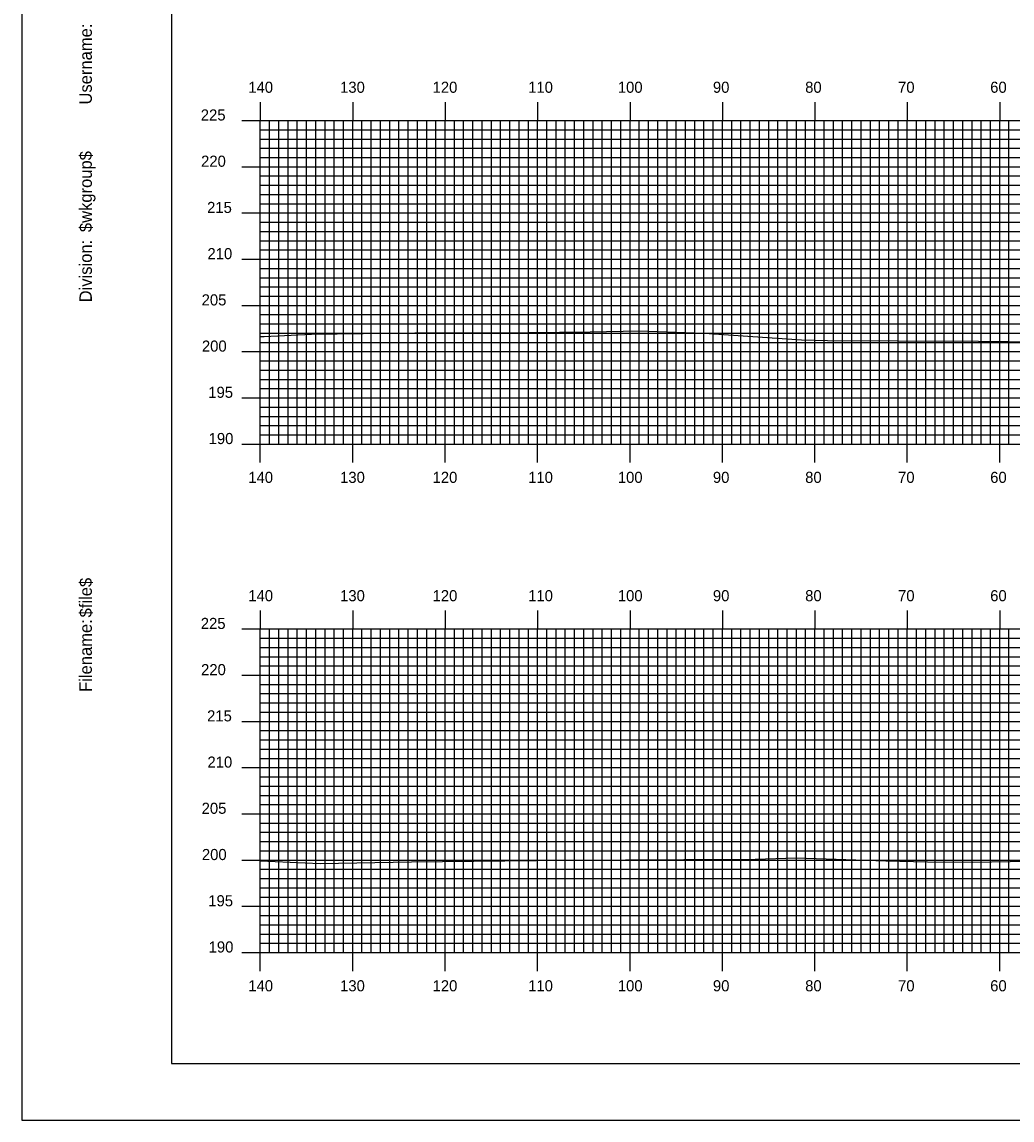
# Model space of a CAD drawing. Extents: x 1811767 to 1812110, y 442591 to 442811.
# Drawn here: x 1811767.1 to 1811874.3, y 442590.5 to 442709.3 of the extents above; entities that cross this region are included whole.
import ezdxf

# ---------------------------------------------------------------- set-up
doc = ezdxf.new("R2010")
doc.units = 0
for name, color, linetype in [('BORDER', 7, 'Continuous'), ('H_V ANNOTATION', 7, 'Continuous'), ('MAJOR', 7, 'Continuous'), ('MINOR', 7, 'Continuous'), ('PLOT BOUNDARY', 7, 'Continuous'), ('S_Roadway_Centerline', 7, 'Continuous')]:
    doc.layers.add(name, color=color, linetype=linetype)

msp = doc.modelspace()

# ---------------------------------------------------------------- linework, layer by layer
at = {"layer": 'BORDER'}
msp.add_lwpolyline([(1811783.32, 442596.67), (1812103.32, 442596.67), (1812103.32, 442806.67), (1811783.32, 442806.67)], close=True, dxfattribs=at)
at = {"layer": 'MAJOR'}
for p, q in [((1811792.92, 442700.67), (1811792.92, 442698.67)), ((1811802.92, 442700.67), (1811802.92, 442698.67)), ((1811812.92, 442700.67), (1811812.92, 442698.67)), ((1811822.92, 442700.67), (1811822.92, 442698.67)), ((1811832.92, 442700.67), (1811832.92, 442698.67)), ((1811842.92, 442700.67), (1811842.92, 442698.67)), ((1811852.92, 442700.67), (1811852.92, 442698.67)), ((1811862.92, 442700.67), (1811862.92, 442698.67)), ((1811872.92, 442700.67), (1811872.92, 442698.67)), ((1811790.91, 442698.67), (1811792.92, 442698.67)), ((1811792.92, 442698.67), (1812072.92, 442698.67)), ((1811792.92, 442663.67), (1811792.92, 442698.67)), ((1811792.92, 442663.67), (1811792.92, 442698.67)), ((1811792.92, 442698.67), (1812072.92, 442698.67)), ((1811802.92, 442663.67), (1811802.92, 442698.67)), ((1811812.92, 442663.67), (1811812.92, 442698.67)), ((1811822.92, 442663.67), (1811822.92, 442698.67)), ((1811832.92, 442663.67), (1811832.92, 442698.67)), ((1811842.92, 442663.67), (1811842.92, 442698.67)), ((1811852.92, 442663.67), (1811852.92, 442698.67)), ((1811862.92, 442663.67), (1811862.92, 442698.67)), ((1811872.92, 442663.67), (1811872.92, 442698.67)), ((1811790.91, 442693.67), (1811792.92, 442693.67)), ((1811792.92, 442693.67), (1812072.92, 442693.67)), ((1811790.91, 442688.67), (1811792.92, 442688.67)), ((1811792.92, 442688.67), (1812072.92, 442688.67)), ((1811790.91, 442683.67), (1811792.92, 442683.67)), ((1811792.92, 442683.67), (1812072.92, 442683.67)), ((1811790.91, 442678.67), (1811792.92, 442678.67)), ((1811792.92, 442678.67), (1812072.92, 442678.67)), ((1811790.91, 442673.67), (1811792.92, 442673.67)), ((1811792.92, 442673.67), (1812072.92, 442673.67)), ((1811790.91, 442668.67), (1811792.92, 442668.67)), ((1811792.92, 442668.67), (1812072.92, 442668.67)), ((1811790.91, 442663.67), (1811792.92, 442663.67)), ((1811792.92, 442663.67), (1812072.92, 442663.67)), ((1811792.92, 442663.67), (1812072.92, 442663.67)), ((1811792.92, 442661.66), (1811792.92, 442663.67)), ((1811802.92, 442661.66), (1811802.92, 442663.67)), ((1811812.92, 442661.66), (1811812.92, 442663.67)), ((1811822.92, 442661.66), (1811822.92, 442663.67)), ((1811832.92, 442661.66), (1811832.92, 442663.67)), ((1811842.92, 442661.66), (1811842.92, 442663.67)), ((1811852.92, 442661.66), (1811852.92, 442663.67)), ((1811862.92, 442661.66), (1811862.92, 442663.67)), ((1811872.92, 442661.66), (1811872.92, 442663.67)), ((1811792.92, 442645.67), (1811792.92, 442643.67)), ((1811802.92, 442645.67), (1811802.92, 442643.67)), ((1811812.92, 442645.67), (1811812.92, 442643.67)), ((1811822.92, 442645.67), (1811822.92, 442643.67)), ((1811832.92, 442645.67), (1811832.92, 442643.67)), ((1811842.92, 442645.67), (1811842.92, 442643.67)), ((1811852.92, 442645.67), (1811852.92, 442643.67)), ((1811862.92, 442645.67), (1811862.92, 442643.67)), ((1811872.92, 442645.67), (1811872.92, 442643.67)), ((1811790.91, 442643.67), (1811792.92, 442643.67)), ((1811792.92, 442643.67), (1812072.92, 442643.67)), ((1811792.92, 442608.67), (1811792.92, 442643.67)), ((1811792.92, 442608.67), (1811792.92, 442643.67)), ((1811792.92, 442643.67), (1812072.92, 442643.67)), ((1811802.92, 442608.67), (1811802.92, 442643.67)), ((1811812.92, 442608.67), (1811812.92, 442643.67)), ((1811822.92, 442608.67), (1811822.92, 442643.67)), ((1811832.92, 442608.67), (1811832.92, 442643.67)), ((1811842.92, 442608.67), (1811842.92, 442643.67)), ((1811852.92, 442608.67), (1811852.92, 442643.67)), ((1811862.92, 442608.67), (1811862.92, 442643.67)), ((1811872.92, 442608.67), (1811872.92, 442643.67)), ((1811790.91, 442638.67), (1811792.92, 442638.67)), ((1811792.92, 442638.67), (1812072.92, 442638.67)), ((1811790.91, 442633.67), (1811792.92, 442633.67)), ((1811792.92, 442633.67), (1812072.92, 442633.67)), ((1811790.91, 442628.67), (1811792.92, 442628.67)), ((1811792.92, 442628.67), (1812072.92, 442628.67)), ((1811790.91, 442623.67), (1811792.92, 442623.67)), ((1811792.92, 442623.67), (1812072.92, 442623.67)), ((1811790.91, 442618.67), (1811792.92, 442618.67)), ((1811792.92, 442618.67), (1812072.92, 442618.67)), ((1811790.91, 442613.67), (1811792.92, 442613.67)), ((1811792.92, 442613.67), (1812072.92, 442613.67)), ((1811790.91, 442608.67), (1811792.92, 442608.67)), ((1811792.92, 442608.67), (1812072.92, 442608.67)), ((1811792.92, 442608.67), (1812072.92, 442608.67)), ((1811792.92, 442606.66), (1811792.92, 442608.67)), ((1811802.92, 442606.66), (1811802.92, 442608.67)), ((1811812.92, 442606.66), (1811812.92, 442608.67)), ((1811822.92, 442606.66), (1811822.92, 442608.67)), ((1811832.92, 442606.66), (1811832.92, 442608.67)), ((1811842.92, 442606.66), (1811842.92, 442608.67)), ((1811852.92, 442606.66), (1811852.92, 442608.67)), ((1811862.92, 442606.66), (1811862.92, 442608.67)), ((1811872.92, 442606.66), (1811872.92, 442608.67))]:
    msp.add_line(p, q, dxfattribs=at)
at = {"layer": 'MINOR'}
for p, q in [((1811793.92, 442663.67), (1811793.92, 442698.67)), ((1811794.92, 442663.67), (1811794.92, 442698.67)), ((1811795.92, 442663.67), (1811795.92, 442698.67)), ((1811796.92, 442663.67), (1811796.92, 442698.67)), ((1811797.92, 442663.67), (1811797.92, 442698.67)), ((1811798.92, 442663.67), (1811798.92, 442698.67)), ((1811799.92, 442663.67), (1811799.92, 442698.67)), ((1811800.92, 442663.67), (1811800.92, 442698.67)), ((1811801.92, 442663.67), (1811801.92, 442698.67)), ((1811803.92, 442663.67), (1811803.92, 442698.67)), ((1811804.92, 442663.67), (1811804.92, 442698.67)), ((1811805.92, 442663.67), (1811805.92, 442698.67)), ((1811806.92, 442663.67), (1811806.92, 442698.67)), ((1811807.92, 442663.67), (1811807.92, 442698.67)), ((1811808.92, 442663.67), (1811808.92, 442698.67)), ((1811809.92, 442663.67), (1811809.92, 442698.67)), ((1811810.92, 442663.67), (1811810.92, 442698.67)), ((1811811.92, 442663.67), (1811811.92, 442698.67)), ((1811813.92, 442663.67), (1811813.92, 442698.67)), ((1811814.92, 442663.67), (1811814.92, 442698.67)), ((1811815.92, 442663.67), (1811815.92, 442698.67)), ((1811816.92, 442663.67), (1811816.92, 442698.67)), ((1811817.92, 442663.67), (1811817.92, 442698.67)), ((1811818.92, 442663.67), (1811818.92, 442698.67)), ((1811819.92, 442663.67), (1811819.92, 442698.67)), ((1811820.92, 442663.67), (1811820.92, 442698.67)), ((1811821.92, 442663.67), (1811821.92, 442698.67)), ((1811823.92, 442663.67), (1811823.92, 442698.67)), ((1811824.92, 442663.67), (1811824.92, 442698.67)), ((1811825.92, 442663.67), (1811825.92, 442698.67)), ((1811826.92, 442663.67), (1811826.92, 442698.67)), ((1811827.92, 442663.67), (1811827.92, 442698.67)), ((1811828.92, 442663.67), (1811828.92, 442698.67)), ((1811829.92, 442663.67), (1811829.92, 442698.67)), ((1811830.92, 442663.67), (1811830.92, 442698.67)), ((1811831.92, 442663.67), (1811831.92, 442698.67)), ((1811833.92, 442663.67), (1811833.92, 442698.67)), ((1811834.92, 442663.67), (1811834.92, 442698.67)), ((1811835.92, 442663.67), (1811835.92, 442698.67)), ((1811836.92, 442663.67), (1811836.92, 442698.67)), ((1811837.92, 442663.67), (1811837.92, 442698.67)), ((1811838.92, 442663.67), (1811838.92, 442698.67)), ((1811839.92, 442663.67), (1811839.92, 442698.67)), ((1811840.92, 442663.67), (1811840.92, 442698.67)), ((1811841.92, 442663.67), (1811841.92, 442698.67)), ((1811843.92, 442663.67), (1811843.92, 442698.67)), ((1811844.92, 442663.67), (1811844.92, 442698.67)), ((1811845.92, 442663.67), (1811845.92, 442698.67)), ((1811846.92, 442663.67), (1811846.92, 442698.67)), ((1811847.92, 442663.67), (1811847.92, 442698.67)), ((1811848.92, 442663.67), (1811848.92, 442698.67)), ((1811849.92, 442663.67), (1811849.92, 442698.67)), ((1811850.92, 442663.67), (1811850.92, 442698.67)), ((1811851.92, 442663.67), (1811851.92, 442698.67)), ((1811853.92, 442663.67), (1811853.92, 442698.67)), ((1811854.92, 442663.67), (1811854.92, 442698.67)), ((1811855.92, 442663.67), (1811855.92, 442698.67)), ((1811856.92, 442663.67), (1811856.92, 442698.67)), ((1811857.92, 442663.67), (1811857.92, 442698.67)), ((1811858.92, 442663.67), (1811858.92, 442698.67)), ((1811859.92, 442663.67), (1811859.92, 442698.67)), ((1811860.92, 442663.67), (1811860.92, 442698.67)), ((1811861.92, 442663.67), (1811861.92, 442698.67)), ((1811863.92, 442663.67), (1811863.92, 442698.67)), ((1811864.92, 442663.67), (1811864.92, 442698.67)), ((1811865.92, 442663.67), (1811865.92, 442698.67)), ((1811866.92, 442663.67), (1811866.92, 442698.67)), ((1811867.92, 442663.67), (1811867.92, 442698.67)), ((1811868.92, 442663.67), (1811868.92, 442698.67)), ((1811869.92, 442663.67), (1811869.92, 442698.67)), ((1811870.92, 442663.67), (1811870.92, 442698.67)), ((1811871.92, 442663.67), (1811871.92, 442698.67)), ((1811873.92, 442663.67), (1811873.92, 442698.67)), ((1811792.92, 442697.67), (1812072.92, 442697.67)), ((1811792.92, 442697.67), (1811794.92, 442697.67)), ((1811792.92, 442696.67), (1812072.92, 442696.67)), ((1811792.92, 442696.67), (1811794.92, 442696.67)), ((1811792.92, 442695.67), (1812072.92, 442695.67)), ((1811792.92, 442695.67), (1811794.92, 442695.67)), ((1811792.92, 442694.67), (1812072.92, 442694.67)), ((1811792.92, 442694.67), (1811794.92, 442694.67)), ((1811792.92, 442692.67), (1812072.92, 442692.67)), ((1811792.92, 442692.67), (1811794.92, 442692.67)), ((1811792.92, 442691.67), (1812072.92, 442691.67)), ((1811792.92, 442691.67), (1811794.92, 442691.67)), ((1811792.92, 442690.67), (1812072.92, 442690.67)), ((1811792.92, 442690.67), (1811794.92, 442690.67)), ((1811792.92, 442689.67), (1812072.92, 442689.67)), ((1811792.92, 442689.67), (1811794.92, 442689.67)), ((1811792.92, 442687.67), (1812072.92, 442687.67)), ((1811792.92, 442687.67), (1811794.92, 442687.67)), ((1811792.92, 442686.67), (1812072.92, 442686.67)), ((1811792.92, 442686.67), (1811794.92, 442686.67)), ((1811792.92, 442685.67), (1812072.92, 442685.67)), ((1811792.92, 442685.67), (1811794.92, 442685.67)), ((1811792.92, 442684.67), (1812072.92, 442684.67)), ((1811792.92, 442684.67), (1811794.92, 442684.67)), ((1811792.92, 442682.67), (1812072.92, 442682.67)), ((1811792.92, 442682.67), (1811794.92, 442682.67)), ((1811792.92, 442681.67), (1812072.92, 442681.67)), ((1811792.92, 442681.67), (1811794.92, 442681.67)), ((1811792.92, 442680.67), (1812072.92, 442680.67)), ((1811792.92, 442680.67), (1811794.92, 442680.67)), ((1811792.92, 442679.67), (1812072.92, 442679.67)), ((1811792.92, 442679.67), (1811794.92, 442679.67)), ((1811792.92, 442677.67), (1812072.92, 442677.67)), ((1811792.92, 442677.67), (1811794.92, 442677.67)), ((1811792.92, 442676.67), (1812072.92, 442676.67)), ((1811792.92, 442676.67), (1811794.92, 442676.67)), ((1811792.92, 442675.67), (1812072.92, 442675.67)), ((1811792.92, 442675.67), (1811794.92, 442675.67)), ((1811792.92, 442674.67), (1812072.92, 442674.67)), ((1811792.92, 442674.67), (1811794.92, 442674.67)), ((1811792.92, 442672.67), (1812072.92, 442672.67)), ((1811792.92, 442672.67), (1811794.92, 442672.67)), ((1811792.92, 442671.67), (1812072.92, 442671.67)), ((1811792.92, 442671.67), (1811794.92, 442671.67)), ((1811792.92, 442670.67), (1812072.92, 442670.67)), ((1811792.92, 442670.67), (1811794.92, 442670.67)), ((1811792.92, 442669.67), (1812072.92, 442669.67)), ((1811792.92, 442669.67), (1811794.92, 442669.67)), ((1811792.92, 442667.67), (1812072.92, 442667.67)), ((1811792.92, 442667.67), (1811794.92, 442667.67)), ((1811792.92, 442666.67), (1812072.92, 442666.67)), ((1811792.92, 442666.67), (1811794.92, 442666.67)), ((1811792.92, 442665.67), (1812072.92, 442665.67)), ((1811792.92, 442665.67), (1811794.92, 442665.67)), ((1811792.92, 442664.67), (1812072.92, 442664.67)), ((1811792.92, 442664.67), (1811794.92, 442664.67)), ((1811793.92, 442608.67), (1811793.92, 442643.67)), ((1811794.92, 442608.67), (1811794.92, 442643.67)), ((1811795.92, 442608.67), (1811795.92, 442643.67)), ((1811796.92, 442608.67), (1811796.92, 442643.67)), ((1811797.92, 442608.67), (1811797.92, 442643.67)), ((1811798.92, 442608.67), (1811798.92, 442643.67)), ((1811799.92, 442608.67), (1811799.92, 442643.67)), ((1811800.92, 442608.67), (1811800.92, 442643.67)), ((1811801.92, 442608.67), (1811801.92, 442643.67)), ((1811803.92, 442608.67), (1811803.92, 442643.67)), ((1811804.92, 442608.67), (1811804.92, 442643.67)), ((1811805.92, 442608.67), (1811805.92, 442643.67)), ((1811806.92, 442608.67), (1811806.92, 442643.67)), ((1811807.92, 442608.67), (1811807.92, 442643.67)), ((1811808.92, 442608.67), (1811808.92, 442643.67)), ((1811809.92, 442608.67), (1811809.92, 442643.67)), ((1811810.92, 442608.67), (1811810.92, 442643.67)), ((1811811.92, 442608.67), (1811811.92, 442643.67)), ((1811813.92, 442608.67), (1811813.92, 442643.67)), ((1811814.92, 442608.67), (1811814.92, 442643.67)), ((1811815.92, 442608.67), (1811815.92, 442643.67)), ((1811816.92, 442608.67), (1811816.92, 442643.67)), ((1811817.92, 442608.67), (1811817.92, 442643.67)), ((1811818.92, 442608.67), (1811818.92, 442643.67)), ((1811819.92, 442608.67), (1811819.92, 442643.67)), ((1811820.92, 442608.67), (1811820.92, 442643.67)), ((1811821.92, 442608.67), (1811821.92, 442643.67)), ((1811823.92, 442608.67), (1811823.92, 442643.67)), ((1811824.92, 442608.67), (1811824.92, 442643.67)), ((1811825.92, 442608.67), (1811825.92, 442643.67)), ((1811826.92, 442608.67), (1811826.92, 442643.67)), ((1811827.92, 442608.67), (1811827.92, 442643.67)), ((1811828.92, 442608.67), (1811828.92, 442643.67)), ((1811829.92, 442608.67), (1811829.92, 442643.67)), ((1811830.92, 442608.67), (1811830.92, 442643.67)), ((1811831.92, 442608.67), (1811831.92, 442643.67)), ((1811833.92, 442608.67), (1811833.92, 442643.67)), ((1811834.92, 442608.67), (1811834.92, 442643.67)), ((1811835.92, 442608.67), (1811835.92, 442643.67)), ((1811836.92, 442608.67), (1811836.92, 442643.67)), ((1811837.92, 442608.67), (1811837.92, 442643.67)), ((1811838.92, 442608.67), (1811838.92, 442643.67)), ((1811839.92, 442608.67), (1811839.92, 442643.67)), ((1811840.92, 442608.67), (1811840.92, 442643.67)), ((1811841.92, 442608.67), (1811841.92, 442643.67)), ((1811843.92, 442608.67), (1811843.92, 442643.67)), ((1811844.92, 442608.67), (1811844.92, 442643.67)), ((1811845.92, 442608.67), (1811845.92, 442643.67)), ((1811846.92, 442608.67), (1811846.92, 442643.67)), ((1811847.92, 442608.67), (1811847.92, 442643.67)), ((1811848.92, 442608.67), (1811848.92, 442643.67)), ((1811849.92, 442608.67), (1811849.92, 442643.67)), ((1811850.92, 442608.67), (1811850.92, 442643.67)), ((1811851.92, 442608.67), (1811851.92, 442643.67)), ((1811853.92, 442608.67), (1811853.92, 442643.67)), ((1811854.92, 442608.67), (1811854.92, 442643.67)), ((1811855.92, 442608.67), (1811855.92, 442643.67)), ((1811856.92, 442608.67), (1811856.92, 442643.67)), ((1811857.92, 442608.67), (1811857.92, 442643.67)), ((1811858.92, 442608.67), (1811858.92, 442643.67)), ((1811859.92, 442608.67), (1811859.92, 442643.67)), ((1811860.92, 442608.67), (1811860.92, 442643.67)), ((1811861.92, 442608.67), (1811861.92, 442643.67)), ((1811863.92, 442608.67), (1811863.92, 442643.67)), ((1811864.92, 442608.67), (1811864.92, 442643.67)), ((1811865.92, 442608.67), (1811865.92, 442643.67)), ((1811866.92, 442608.67), (1811866.92, 442643.67)), ((1811867.92, 442608.67), (1811867.92, 442643.67)), ((1811868.92, 442608.67), (1811868.92, 442643.67)), ((1811869.92, 442608.67), (1811869.92, 442643.67)), ((1811870.92, 442608.67), (1811870.92, 442643.67)), ((1811871.92, 442608.67), (1811871.92, 442643.67)), ((1811873.92, 442608.67), (1811873.92, 442643.67)), ((1811792.92, 442642.67), (1812072.92, 442642.67)), ((1811792.92, 442642.67), (1811794.92, 442642.67)), ((1811792.92, 442641.67), (1812072.92, 442641.67)), ((1811792.92, 442641.67), (1811794.92, 442641.67)), ((1811792.92, 442640.67), (1812072.92, 442640.67)), ((1811792.92, 442640.67), (1811794.92, 442640.67)), ((1811792.92, 442639.67), (1812072.92, 442639.67)), ((1811792.92, 442639.67), (1811794.92, 442639.67)), ((1811792.92, 442637.67), (1812072.92, 442637.67)), ((1811792.92, 442637.67), (1811794.92, 442637.67)), ((1811792.92, 442636.67), (1812072.92, 442636.67)), ((1811792.92, 442636.67), (1811794.92, 442636.67)), ((1811792.92, 442635.67), (1812072.92, 442635.67)), ((1811792.92, 442635.67), (1811794.92, 442635.67)), ((1811792.92, 442634.67), (1812072.92, 442634.67)), ((1811792.92, 442634.67), (1811794.92, 442634.67)), ((1811792.92, 442632.67), (1812072.92, 442632.67)), ((1811792.92, 442632.67), (1811794.92, 442632.67)), ((1811792.92, 442631.67), (1812072.92, 442631.67)), ((1811792.92, 442631.67), (1811794.92, 442631.67)), ((1811792.92, 442630.67), (1812072.92, 442630.67)), ((1811792.92, 442630.67), (1811794.92, 442630.67)), ((1811792.92, 442629.67), (1812072.92, 442629.67)), ((1811792.92, 442629.67), (1811794.92, 442629.67)), ((1811792.92, 442627.67), (1812072.92, 442627.67)), ((1811792.92, 442627.67), (1811794.92, 442627.67)), ((1811792.92, 442626.67), (1812072.92, 442626.67)), ((1811792.92, 442626.67), (1811794.92, 442626.67)), ((1811792.92, 442625.67), (1812072.92, 442625.67)), ((1811792.92, 442625.67), (1811794.92, 442625.67)), ((1811792.92, 442624.67), (1812072.92, 442624.67)), ((1811792.92, 442624.67), (1811794.92, 442624.67)), ((1811792.92, 442622.67), (1812072.92, 442622.67)), ((1811792.92, 442622.67), (1811794.92, 442622.67)), ((1811792.92, 442621.67), (1812072.92, 442621.67)), ((1811792.92, 442621.67), (1811794.92, 442621.67)), ((1811792.92, 442620.67), (1812072.92, 442620.67)), ((1811792.92, 442620.67), (1811794.92, 442620.67)), ((1811792.92, 442619.67), (1812072.92, 442619.67)), ((1811792.92, 442619.67), (1811794.92, 442619.67)), ((1811792.92, 442617.67), (1812072.92, 442617.67)), ((1811792.92, 442617.67), (1811794.92, 442617.67)), ((1811792.92, 442616.67), (1812072.92, 442616.67)), ((1811792.92, 442616.67), (1811794.92, 442616.67)), ((1811792.92, 442615.67), (1812072.92, 442615.67)), ((1811792.92, 442615.67), (1811794.92, 442615.67)), ((1811792.92, 442614.67), (1812072.92, 442614.67)), ((1811792.92, 442614.67), (1811794.92, 442614.67)), ((1811792.92, 442612.67), (1812072.92, 442612.67)), ((1811792.92, 442612.67), (1811794.92, 442612.67)), ((1811792.92, 442611.67), (1812072.92, 442611.67)), ((1811792.92, 442611.67), (1811794.92, 442611.67)), ((1811792.92, 442610.67), (1812072.92, 442610.67)), ((1811792.92, 442610.67), (1811794.92, 442610.67)), ((1811792.92, 442609.67), (1812072.92, 442609.67)), ((1811792.92, 442609.67), (1811794.92, 442609.67))]:
    msp.add_line(p, q, dxfattribs=at)
at = {"layer": 'PLOT BOUNDARY'}
msp.add_lwpolyline([(1811767.13, 442590.55), (1812107.13, 442590.55), (1812107.13, 442810.55), (1811767.13, 442810.55)], close=True, dxfattribs=at)
at = {"layer": 'S_Roadway_Centerline'}
for points in [[(1811792.92, 442675.29), (1811793.32, 442675.31), (1811798.45, 442675.57), (1811809.64, 442675.71), (1811818.69, 442675.7), (1811828.62, 442675.81), (1811833.93, 442675.93), (1811840.94, 442675.65), (1811851.46, 442674.96), (1811854.3, 442674.89), (1811861.95, 442674.83), (1811870.61, 442674.79), (1811880.53, 442674.68), (1811891.99, 442674.77), (1811903.84, 442674.62), (1811919.63, 442673.92), (1811927.29, 442673.55), (1811944.65, 442672.84), (1811951.76, 442672.74), (1811969.82, 442672.4), (1811979.59, 442672.39), (1811993.71, 442672.13)], [(1811792.92, 442618.59), (1811799.41, 442618.3), (1811809.29, 442618.47), (1811826.12, 442618.65), (1811838.75, 442618.74), (1811846.45, 442618.78), (1811850.91, 442618.92), (1811860.59, 442618.59), (1811865.11, 442618.47), (1811870, 442618.46), (1811884.1, 442618.7)]]:
    msp.add_lwpolyline(points, dxfattribs=at)

# ---------------------------------------------------------------- texts
at = {"layer": 'BORDER'}
for s, p in [('Username:', (1811774.69, 442700.4)), ('$wkgroup$', (1811774.69, 442686.6)), ('Division:', (1811774.69, 442679)), ('$file$', (1811774.69, 442644.92)), ('Filename:', (1811774.69, 442636.86))]:
    msp.add_text(s, height=1.339, rotation=90, dxfattribs=at).set_placement(p)
at = {"layer": 'H_V ANNOTATION'}
for s, p in [('140', (1811791.62, 442701.67)), ('130', (1811801.55, 442701.67)), ('120', (1811811.56, 442701.67)), ('110', (1811821.9, 442701.67)), ('100', (1811831.6, 442701.67)), ('90', (1811841.89, 442701.67)), ('80', (1811851.87, 442701.67)), ('70', (1811861.92, 442701.67)), ('60', (1811871.89, 442701.67)), ('225', (1811786.48, 442698.67)), ('220', (1811786.51, 442693.67)), ('215', (1811787.16, 442688.67)), ('210', (1811787.2, 442683.67)), ('205', (1811786.57, 442678.67)), ('200', (1811786.6, 442673.67)), ('195', (1811787.29, 442668.67)), ('190', (1811787.33, 442663.67)), ('140', (1811791.62, 442659.47)), ('130', (1811801.55, 442659.47)), ('120', (1811811.56, 442659.47)), ('110', (1811821.9, 442659.47)), ('100', (1811831.6, 442659.47)), ('90', (1811841.89, 442659.47)), ('80', (1811851.87, 442659.47)), ('70', (1811861.92, 442659.47)), ('60', (1811871.89, 442659.47)), ('140', (1811791.62, 442646.67)), ('130', (1811801.55, 442646.67)), ('120', (1811811.56, 442646.67)), ('110', (1811821.9, 442646.67)), ('100', (1811831.6, 442646.67)), ('90', (1811841.89, 442646.67)), ('80', (1811851.87, 442646.67)), ('70', (1811861.92, 442646.67)), ('60', (1811871.89, 442646.67)), ('225', (1811786.48, 442643.67)), ('220', (1811786.51, 442638.67)), ('215', (1811787.16, 442633.67)), ('210', (1811787.2, 442628.67)), ('205', (1811786.57, 442623.67)), ('200', (1811786.6, 442618.67)), ('195', (1811787.29, 442613.67)), ('190', (1811787.33, 442608.67)), ('140', (1811791.62, 442604.47)), ('130', (1811801.55, 442604.47)), ('120', (1811811.56, 442604.47)), ('110', (1811821.9, 442604.47)), ('100', (1811831.6, 442604.47)), ('90', (1811841.89, 442604.47)), ('80', (1811851.87, 442604.47)), ('70', (1811861.92, 442604.47)), ('60', (1811871.89, 442604.47))]:
    msp.add_text(s, height=1.2, dxfattribs=at).set_placement(p)
at = {"layer": 'MAJOR'}
for p in [(1811792.91, 442663.67), (1811792.91, 442608.67)]:
    msp.add_text('-', height=0.012, dxfattribs=at).set_placement(p)

doc.saveas('drawing.dxf')
